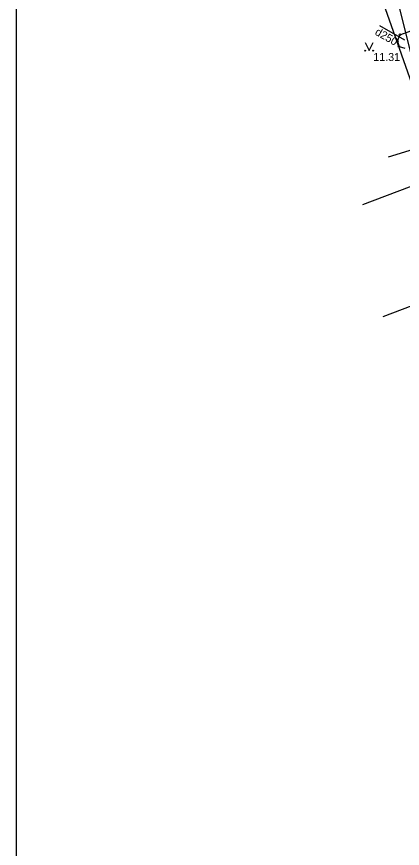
# Model space of a CAD drawing. Extents: x 503353 to 504004, y 304662 to 305049.
# Drawn here: x 503353 to 503377.1, y 304935.2 to 304987.1 of the extents above; entities that cross this region are included whole.
import ezdxf

# ---------------------------------------------------------------- set-up
doc = ezdxf.new("R2010")
doc.units = 0
for name, color, linetype in [('24', 7, 'Continuous'), ('APGR_SARK_####_####_#', 7, 'Continuous'), ('DREN_VADP_####_####_#', 7, 'Continuous'), ('LKAN_ELEM_SPDK_TKST_#', 7, 'Continuous'), ('RAMI_PLAN_####_TKST_#', 7, 'Continuous'), ('RAMI_UZMR_####_####_#', 7, 'Continuous'), ('RELJ_ELEM_####_####_#', 7, 'Continuous'), ('SKAN_DETP_SPDK_####_#', 7, 'Continuous'), ('SKAN_VADP_PAST_####_#', 7, 'Continuous'), ('SKAN_VADP_PAST_TKST_#', 7, 'Continuous'), ('TERT_ELEM_####_####_#', 7, 'Continuous')]:
    doc.layers.add(name, color=color, linetype=linetype)

msp = doc.modelspace()

# ---------------------------------------------------------------- linework, layer by layer
at = {"layer": '24'}
msp.add_line((503375.886, 304968.402), (503401.316, 304977.953), dxfattribs=at)
at = {"layer": 'APGR_SARK_####_####_#'}
msp.add_line((503374.603, 304975.397), (503379.694, 304977.309), dxfattribs=at)
at = {"layer": 'DREN_VADP_####_####_#'}
for q in [(503371.327, 305001.016), (503376.193, 304978.347)]:
    msp.add_line((503378.974, 304979.201), q, dxfattribs=at)
at = {"layer": 'RAMI_PLAN_####_TKST_#'}
msp.add_lwpolyline([(503550.18, 304891.905), (503352.996, 304891.905), (503352.996, 305034.51), (503550.18, 305034.51)], close=True, dxfattribs=at)
at = {"layer": 'RAMI_UZMR_####_####_#'}
msp.add_lwpolyline([(503407.219, 305023.925), (503368.776, 305020.183), (503379.431, 304977.462), (503383.452, 304957.421), (503396.867, 304960.598), (503416.959, 304959.032), (503433.698, 304951.36), (503608.791, 304871.751), (503642.724, 304858.177), (503694.651, 304834.724), (503842.283, 304765.867)], dxfattribs=at)
at = {"layer": 'RELJ_ELEM_####_####_#'}
for centre in [(503376.926, 304985.997), (503376.765, 304985.58), (503376.873, 304985.259)]:
    msp.add_circle(centre, 0.05, dxfattribs=at)
at = {"layer": 'SKAN_DETP_SPDK_####_#'}
for points in [[(503376.765, 304985.58), (503376.926, 304985.997)], [(503376.926, 304985.997), (503377.661, 304986.259)], [(503376.765, 304985.58), (503376.873, 304985.259), (503377.227, 304985.153)]]:
    msp.add_lwpolyline(points, dxfattribs=at)
at = {"layer": 'SKAN_VADP_PAST_####_#'}
msp.add_line((503375.647, 304986.561), (503377.209, 304985.67), dxfattribs=at)
at = {"layer": 'TERT_ELEM_####_####_#'}
for p, q in [((503374.75, 304985.5), (503375, 304985)), ((503375, 304985), (503375.25, 304985.5))]:
    msp.add_line(p, q, dxfattribs=at)
for centre, radius in [((503374.75, 304985), 0.028), ((503375.25, 304985), 0.0263)]:
    msp.add_circle(centre, radius, dxfattribs=at)

# ---------------------------------------------------------------- texts
at = {"layer": 'LKAN_ELEM_SPDK_TKST_#'}
msp.add_text(' 11.31', height=0.5, dxfattribs=at).set_placement((503375.076, 304984.352))
at = {"layer": 'SKAN_VADP_PAST_TKST_#'}
msp.add_text('d250', height=0.5, rotation=330.2881, dxfattribs=at).set_placement((503375.319, 304986.028))

doc.saveas('drawing.dxf')
